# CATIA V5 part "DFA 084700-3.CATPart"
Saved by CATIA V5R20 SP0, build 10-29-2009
Part number: DFA 084700-3
Revision: ANY
Definition: UNKNOWN
Nomenclature: DFA 084700-3
Source: Unknown
Bounding box of the stored display mesh (mm): x -2.687 to 2.687, y -2.475 to 2.475, z -2.5 to 2.5
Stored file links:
  C:\Users\Utente\Desktop\IO LAVORO\3D X SITO CF\CUMSA\3D files FA\FA 084705-21\DFA 084700-3.CATPart
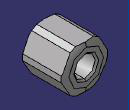
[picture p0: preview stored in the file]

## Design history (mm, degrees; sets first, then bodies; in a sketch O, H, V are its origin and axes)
Body1 "Chaflán4" (main body)
  Solid1: solid without history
